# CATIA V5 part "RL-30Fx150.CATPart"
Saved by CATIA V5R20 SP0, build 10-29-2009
Part number: _RL-30Fx150
Definition: NONE
Nomenclature: _RL-30Fx150
Source: Unknown
Description: PART-_RL-30Fx150-DESC
Bounding box of the stored display mesh (mm): x -150 to 14, y -16 to 16, z -16 to 16
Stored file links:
  C:\Users\Utente\Desktop\IO LAVORO\3D X SITO CF\X SITO\PLASTICA\RLF\RL-30Fx150.CATPart
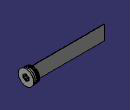
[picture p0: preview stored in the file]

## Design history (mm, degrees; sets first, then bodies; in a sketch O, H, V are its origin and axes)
Body1 "_RL-30Fx150" (main body)
  Solid1: solid without history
